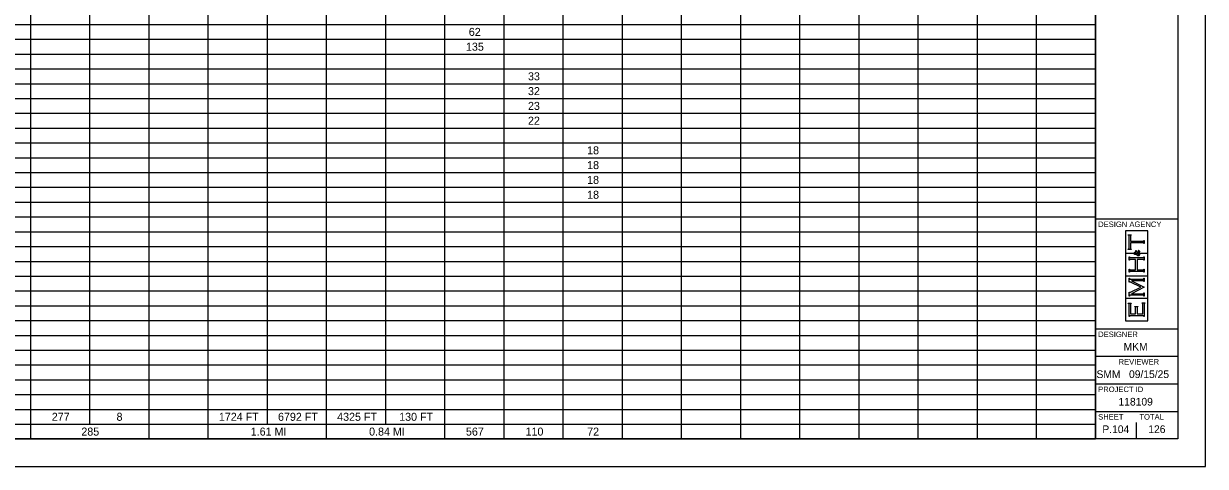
# Model space of a CAD drawing. Extents: x 0 to 34, y 0 to 22.
# Drawn here: x 12.5 to 34, y 0 to 8.05 of the extents above; entities that cross this region are included whole.
import ezdxf

# ---------------------------------------------------------------- set-up
doc = ezdxf.new("R2010")
doc.units = 0
for name, color, linetype in [('SH_Border', 7, 'Continuous'), ('SH_Cut_Line', 7, 'Continuous'), ('SH_Data', 7, 'Continuous'), ('SH_Text', 7, 'Continuous')]:
    doc.layers.add(name, color=color, linetype=linetype)

msp = doc.modelspace()

# ---------------------------------------------------------------- linework, layer by layer
at = {"layer": 'SH_Border'}
for p, q in [((32, 0.5), (32, 21.5)), ((32, 4.5), (33.5, 4.5)), ((32, 2.5), (33.5, 2.5)), ((32, 2), (33.5, 2)), ((32, 1.5), (33.5, 1.5)), ((32, 1), (33.5, 1))]:
    msp.add_line(p, q, dxfattribs=at)
msp.add_lwpolyline([(1.5, 21.5), (33.5, 21.5), (33.5, 0.5), (1.5, 0.5)], close=True, dxfattribs=at)
at = {"layer": 'SH_Cut_Line'}
msp.add_lwpolyline([(0, 0), (34, 0), (34, 22), (0, 22)], close=True, dxfattribs=at)
at = {"layer": 'SH_Data'}
for p, q in [((32.952, 4.279), (32.547, 4.279)), ((32.547, 4.279), (32.547, 3.875)), ((32.598, 4.204), (32.598, 4.211)), ((32.598, 4.211), (32.65, 4.211)), ((32.603, 4.203), (32.598, 4.204)), ((32.606, 4.201), (32.603, 4.203)), ((32.608, 4.199), (32.606, 4.201)), ((32.61, 4.196), (32.608, 4.199)), ((32.611, 4.192), (32.61, 4.196)), ((32.611, 4.187), (32.611, 4.192)), ((32.611, 3.968), (32.611, 4.187)), ((32.638, 4.196), (32.637, 4.192)), ((32.637, 4.192), (32.637, 4.187)), ((32.637, 4.187), (32.637, 4.093)), ((32.637, 4.093), (32.864, 4.093)), ((32.64, 4.199), (32.638, 4.196)), ((32.642, 4.201), (32.64, 4.199)), ((32.645, 4.203), (32.642, 4.201)), ((32.65, 4.204), (32.645, 4.203)), ((32.65, 4.211), (32.65, 4.204)), ((32.864, 4.093), (32.869, 4.093)), ((32.869, 4.093), (32.873, 4.094)), ((32.873, 4.094), (32.876, 4.096)), ((32.876, 4.096), (32.878, 4.097)), ((32.878, 4.097), (32.88, 4.101)), ((32.88, 4.101), (32.881, 4.106)), ((32.881, 4.106), (32.888, 4.106)), ((32.888, 4.106), (32.888, 4.048)), ((32.952, 3.875), (32.952, 4.279)), ((32.547, 3.875), (32.696, 3.875)), ((32.696, 3.869), (32.547, 3.869)), ((32.547, 3.869), (32.547, 3.465)), ((32.598, 3.95), (32.603, 3.951)), ((32.598, 3.944), (32.598, 3.95)), ((32.65, 3.944), (32.598, 3.944)), ((32.603, 3.951), (32.606, 3.953)), ((32.606, 3.953), (32.608, 3.955)), ((32.608, 3.955), (32.61, 3.958)), ((32.61, 3.958), (32.611, 3.962)), ((32.611, 3.962), (32.611, 3.968)), ((32.864, 4.061), (32.637, 4.061)), ((32.637, 4.061), (32.637, 3.968)), ((32.637, 3.968), (32.637, 3.962)), ((32.637, 3.962), (32.638, 3.958)), ((32.638, 3.958), (32.64, 3.955)), ((32.64, 3.955), (32.642, 3.953)), ((32.642, 3.953), (32.645, 3.951)), ((32.645, 3.951), (32.65, 3.95)), ((32.65, 3.95), (32.65, 3.944)), ((32.696, 3.875), (32.696, 3.869)), ((32.703, 3.879), (32.705, 3.883)), ((32.703, 3.873), (32.703, 3.879)), ((32.703, 3.868), (32.703, 3.873)), ((32.705, 3.883), (32.708, 3.887)), ((32.708, 3.887), (32.711, 3.89)), ((32.709, 3.879), (32.708, 3.876)), ((32.708, 3.876), (32.708, 3.873)), ((32.708, 3.873), (32.708, 3.869)), ((32.708, 3.869), (32.71, 3.866)), ((32.712, 3.881), (32.709, 3.879)), ((32.711, 3.89), (32.715, 3.892)), ((32.714, 3.883), (32.712, 3.881)), ((32.716, 3.884), (32.714, 3.883)), ((32.715, 3.892), (32.72, 3.892)), ((32.72, 3.884), (32.716, 3.884)), ((32.72, 3.892), (32.725, 3.892)), ((32.724, 3.884), (32.72, 3.884)), ((32.728, 3.882), (32.724, 3.884)), ((32.725, 3.892), (32.729, 3.89)), ((32.731, 3.88), (32.728, 3.882)), ((32.729, 3.89), (32.732, 3.887)), ((32.734, 3.877), (32.731, 3.88)), ((32.732, 3.887), (32.736, 3.883)), ((32.737, 3.872), (32.734, 3.877)), ((32.736, 3.883), (32.74, 3.878)), ((32.74, 3.867), (32.737, 3.872)), ((32.738, 3.893), (32.738, 3.922)), ((32.738, 3.922), (32.741, 3.922)), ((32.741, 3.893), (32.738, 3.893)), ((32.74, 3.878), (32.744, 3.869)), ((32.741, 3.922), (32.741, 3.918)), ((32.741, 3.918), (32.742, 3.915)), ((32.742, 3.896), (32.741, 3.895)), ((32.741, 3.895), (32.741, 3.893)), ((32.742, 3.915), (32.743, 3.913)), ((32.743, 3.897), (32.742, 3.896)), ((32.743, 3.913), (32.745, 3.911)), ((32.745, 3.899), (32.743, 3.897)), ((32.744, 3.869), (32.754, 3.875)), ((32.745, 3.911), (32.749, 3.908)), ((32.746, 3.899), (32.745, 3.899)), ((32.748, 3.899), (32.746, 3.899)), ((32.755, 3.899), (32.748, 3.899)), ((32.749, 3.908), (32.756, 3.904)), ((32.754, 3.875), (32.764, 3.881)), ((32.763, 3.895), (32.755, 3.899)), ((32.756, 3.904), (32.763, 3.9)), ((32.763, 3.9), (32.77, 3.896)), ((32.772, 3.887), (32.763, 3.895)), ((32.764, 3.881), (32.772, 3.887)), ((32.774, 3.872), (32.768, 3.867)), ((32.77, 3.896), (32.776, 3.891)), ((32.782, 3.878), (32.774, 3.872)), ((32.776, 3.891), (32.781, 3.895)), ((32.779, 3.923), (32.781, 3.926)), ((32.782, 3.922), (32.779, 3.923)), ((32.781, 3.926), (32.787, 3.924)), ((32.781, 3.895), (32.784, 3.898)), ((32.785, 3.921), (32.782, 3.922)), ((32.786, 3.873), (32.782, 3.878)), ((32.784, 3.898), (32.786, 3.901)), ((32.786, 3.919), (32.785, 3.921)), ((32.788, 3.917), (32.786, 3.919)), ((32.786, 3.901), (32.788, 3.904)), ((32.791, 3.886), (32.786, 3.881)), ((32.786, 3.881), (32.791, 3.876)), ((32.788, 3.869), (32.786, 3.873)), ((32.787, 3.924), (32.792, 3.921)), ((32.789, 3.914), (32.788, 3.917)), ((32.788, 3.904), (32.789, 3.908)), ((32.79, 3.867), (32.788, 3.869)), ((32.789, 3.911), (32.789, 3.914)), ((32.789, 3.908), (32.789, 3.911)), ((32.794, 3.89), (32.791, 3.886)), ((32.791, 3.876), (32.795, 3.87)), ((32.792, 3.921), (32.795, 3.918)), ((32.796, 3.894), (32.794, 3.89)), ((32.795, 3.918), (32.798, 3.914)), ((32.795, 3.87), (32.797, 3.866)), ((32.798, 3.897), (32.796, 3.894)), ((32.798, 3.914), (32.799, 3.91)), ((32.799, 3.901), (32.798, 3.897)), ((32.799, 3.91), (32.799, 3.905)), ((32.799, 3.905), (32.799, 3.901)), ((32.803, 3.869), (32.799, 3.875)), ((32.799, 3.875), (32.952, 3.875)), ((32.952, 3.869), (32.803, 3.869)), ((32.87, 4.061), (32.864, 4.061)), ((32.874, 4.06), (32.87, 4.061)), ((32.876, 4.059), (32.874, 4.06)), ((32.878, 4.057), (32.876, 4.059)), ((32.88, 4.053), (32.878, 4.057)), ((32.881, 4.048), (32.88, 4.053)), ((32.888, 4.048), (32.881, 4.048)), ((32.952, 3.465), (32.952, 3.869)), ((32.611, 3.749), (32.611, 3.807)), ((32.611, 3.807), (32.617, 3.807)), ((32.617, 3.749), (32.611, 3.749)), ((32.617, 3.807), (32.619, 3.802)), ((32.618, 3.754), (32.617, 3.749)), ((32.62, 3.758), (32.618, 3.754)), ((32.619, 3.802), (32.62, 3.798)), ((32.62, 3.798), (32.623, 3.797)), ((32.623, 3.76), (32.62, 3.758)), ((32.623, 3.797), (32.625, 3.795)), ((32.625, 3.761), (32.623, 3.76)), ((32.625, 3.795), (32.629, 3.794)), ((32.629, 3.762), (32.625, 3.761)), ((32.629, 3.794), (32.635, 3.794)), ((32.635, 3.762), (32.629, 3.762)), ((32.635, 3.794), (32.864, 3.794)), ((32.732, 3.762), (32.635, 3.762)), ((32.705, 3.863), (32.703, 3.868)), ((32.708, 3.858), (32.705, 3.863)), ((32.712, 3.853), (32.708, 3.858)), ((32.71, 3.866), (32.712, 3.864)), ((32.712, 3.864), (32.715, 3.862)), ((32.718, 3.85), (32.712, 3.853)), ((32.715, 3.862), (32.718, 3.861)), ((32.718, 3.861), (32.721, 3.861)), ((32.726, 3.85), (32.718, 3.85)), ((32.721, 3.861), (32.723, 3.861)), ((32.723, 3.861), (32.725, 3.862)), ((32.725, 3.862), (32.728, 3.862)), ((32.729, 3.85), (32.726, 3.85)), ((32.728, 3.862), (32.731, 3.863)), ((32.731, 3.85), (32.729, 3.85)), ((32.731, 3.863), (32.735, 3.865)), ((32.734, 3.851), (32.731, 3.85)), ((32.732, 3.572), (32.732, 3.762)), ((32.737, 3.852), (32.734, 3.851)), ((32.735, 3.865), (32.74, 3.867)), ((32.741, 3.853), (32.737, 3.852)), ((32.746, 3.855), (32.741, 3.853)), ((32.752, 3.844), (32.746, 3.855)), ((32.756, 3.86), (32.751, 3.857)), ((32.751, 3.857), (32.754, 3.852)), ((32.757, 3.837), (32.752, 3.844)), ((32.754, 3.852), (32.757, 3.848)), ((32.761, 3.863), (32.756, 3.86)), ((32.757, 3.848), (32.761, 3.845)), ((32.763, 3.833), (32.757, 3.837)), ((32.864, 3.762), (32.759, 3.762)), ((32.759, 3.762), (32.759, 3.572)), ((32.764, 3.865), (32.761, 3.863)), ((32.761, 3.845), (32.765, 3.843)), ((32.768, 3.829), (32.763, 3.833)), ((32.768, 3.867), (32.764, 3.865)), ((32.765, 3.843), (32.769, 3.841)), ((32.774, 3.827), (32.768, 3.829)), ((32.769, 3.841), (32.773, 3.841)), ((32.773, 3.841), (32.778, 3.841)), ((32.779, 3.827), (32.774, 3.827)), ((32.778, 3.841), (32.782, 3.843)), ((32.785, 3.827), (32.779, 3.827)), ((32.782, 3.843), (32.786, 3.846)), ((32.79, 3.829), (32.785, 3.827)), ((32.786, 3.846), (32.789, 3.849)), ((32.789, 3.849), (32.791, 3.853)), ((32.791, 3.864), (32.79, 3.867)), ((32.793, 3.834), (32.79, 3.829)), ((32.791, 3.861), (32.791, 3.864)), ((32.791, 3.859), (32.791, 3.861)), ((32.791, 3.853), (32.791, 3.859)), ((32.797, 3.838), (32.793, 3.834)), ((32.797, 3.866), (32.798, 3.861)), ((32.799, 3.844), (32.797, 3.838)), ((32.798, 3.861), (32.799, 3.857)), ((32.799, 3.857), (32.799, 3.852)), ((32.799, 3.852), (32.799, 3.844)), ((32.864, 3.794), (32.869, 3.794)), ((32.87, 3.762), (32.864, 3.762)), ((32.869, 3.794), (32.873, 3.795)), ((32.874, 3.761), (32.87, 3.762)), ((32.873, 3.795), (32.876, 3.797)), ((32.876, 3.76), (32.874, 3.761)), ((32.876, 3.797), (32.878, 3.798)), ((32.878, 3.758), (32.876, 3.76)), ((32.878, 3.798), (32.88, 3.802)), ((32.88, 3.754), (32.878, 3.758)), ((32.88, 3.802), (32.881, 3.807)), ((32.881, 3.749), (32.88, 3.754)), ((32.881, 3.807), (32.888, 3.807)), ((32.888, 3.749), (32.881, 3.749)), ((32.888, 3.807), (32.888, 3.749)), ((32.547, 3.465), (32.952, 3.465)), ((32.952, 3.459), (32.547, 3.459)), ((32.547, 3.459), (32.547, 3.055)), ((32.611, 3.527), (32.611, 3.585)), ((32.611, 3.585), (32.617, 3.585)), ((32.617, 3.527), (32.611, 3.527)), ((32.617, 3.585), (32.619, 3.58)), ((32.618, 3.532), (32.617, 3.527)), ((32.62, 3.536), (32.618, 3.532)), ((32.619, 3.58), (32.62, 3.576)), ((32.62, 3.576), (32.623, 3.574)), ((32.623, 3.537), (32.62, 3.536)), ((32.623, 3.574), (32.625, 3.573)), ((32.625, 3.539), (32.623, 3.537)), ((32.625, 3.573), (32.629, 3.572)), ((32.629, 3.54), (32.625, 3.539)), ((32.629, 3.572), (32.635, 3.572)), ((32.635, 3.54), (32.629, 3.54)), ((32.635, 3.572), (32.732, 3.572)), ((32.864, 3.54), (32.635, 3.54)), ((32.75, 3.5), (32.75, 3.5)), ((32.759, 3.572), (32.864, 3.572)), ((32.864, 3.572), (32.87, 3.572)), ((32.87, 3.54), (32.864, 3.54)), ((32.87, 3.572), (32.874, 3.573)), ((32.874, 3.539), (32.87, 3.54)), ((32.874, 3.573), (32.876, 3.574)), ((32.876, 3.538), (32.874, 3.539)), ((32.876, 3.574), (32.878, 3.576)), ((32.878, 3.536), (32.876, 3.538)), ((32.878, 3.576), (32.88, 3.58)), ((32.88, 3.532), (32.878, 3.536)), ((32.88, 3.58), (32.881, 3.585)), ((32.881, 3.527), (32.88, 3.532)), ((32.881, 3.585), (32.888, 3.585)), ((32.888, 3.527), (32.881, 3.527)), ((32.888, 3.585), (32.888, 3.527)), ((32.952, 3.055), (32.952, 3.459)), ((32.611, 3.345), (32.611, 3.418)), ((32.611, 3.418), (32.617, 3.418)), ((32.617, 3.345), (32.611, 3.345)), ((32.617, 3.418), (32.619, 3.412)), ((32.62, 3.352), (32.617, 3.345)), ((32.619, 3.412), (32.62, 3.409)), ((32.62, 3.409), (32.623, 3.407)), ((32.622, 3.355), (32.62, 3.352)), ((32.626, 3.355), (32.622, 3.355)), ((32.623, 3.407), (32.625, 3.405)), ((32.625, 3.405), (32.629, 3.405)), ((32.629, 3.355), (32.626, 3.355)), ((32.629, 3.405), (32.635, 3.405)), ((32.633, 3.353), (32.629, 3.355)), ((32.64, 3.35), (32.633, 3.353)), ((32.635, 3.405), (32.864, 3.405)), ((32.825, 3.257), (32.64, 3.35)), ((32.641, 3.165), (32.825, 3.257)), ((32.864, 3.373), (32.654, 3.373)), ((32.654, 3.373), (32.888, 3.255)), ((32.888, 3.255), (32.654, 3.138)), ((32.864, 3.405), (32.869, 3.405)), ((32.87, 3.373), (32.864, 3.373)), ((32.869, 3.405), (32.873, 3.405)), ((32.874, 3.372), (32.87, 3.373)), ((32.873, 3.405), (32.876, 3.407)), ((32.876, 3.37), (32.874, 3.372)), ((32.876, 3.407), (32.878, 3.409)), ((32.878, 3.369), (32.876, 3.37)), ((32.878, 3.409), (32.88, 3.412)), ((32.88, 3.365), (32.878, 3.369)), ((32.88, 3.412), (32.881, 3.418)), ((32.881, 3.36), (32.88, 3.365)), ((32.881, 3.418), (32.888, 3.418)), ((32.888, 3.36), (32.881, 3.36)), ((32.888, 3.418), (32.888, 3.36)), ((32.547, 3.055), (32.952, 3.055)), ((32.952, 3.049), (32.547, 3.049)), ((32.547, 3.049), (32.547, 2.645)), ((32.611, 3.096), (32.611, 3.168)), ((32.611, 3.168), (32.617, 3.168)), ((32.617, 3.096), (32.611, 3.096)), ((32.617, 3.168), (32.62, 3.162)), ((32.618, 3.102), (32.617, 3.096)), ((32.62, 3.105), (32.618, 3.102)), ((32.62, 3.162), (32.622, 3.158)), ((32.623, 3.107), (32.62, 3.105)), ((32.622, 3.158), (32.626, 3.158)), ((32.625, 3.109), (32.623, 3.107)), ((32.629, 3.109), (32.625, 3.109)), ((32.626, 3.158), (32.627, 3.158)), ((32.627, 3.158), (32.633, 3.161)), ((32.635, 3.109), (32.629, 3.109)), ((32.633, 3.161), (32.641, 3.165)), ((32.864, 3.109), (32.635, 3.109)), ((32.654, 3.138), (32.864, 3.138)), ((32.864, 3.138), (32.869, 3.138)), ((32.87, 3.109), (32.864, 3.109)), ((32.869, 3.138), (32.873, 3.139)), ((32.874, 3.109), (32.87, 3.109)), ((32.873, 3.139), (32.876, 3.141)), ((32.876, 3.107), (32.874, 3.109)), ((32.876, 3.141), (32.878, 3.143)), ((32.878, 3.105), (32.876, 3.107)), ((32.878, 3.143), (32.88, 3.146)), ((32.88, 3.102), (32.878, 3.105)), ((32.88, 3.146), (32.881, 3.151)), ((32.881, 3.096), (32.88, 3.102)), ((32.881, 3.151), (32.888, 3.151)), ((32.888, 3.096), (32.881, 3.096)), ((32.888, 3.151), (32.888, 3.096)), ((32.952, 2.645), (32.952, 3.049)), ((32.598, 2.962), (32.598, 2.969)), ((32.598, 2.969), (32.65, 2.969)), ((32.603, 2.961), (32.598, 2.962)), ((32.606, 2.959), (32.603, 2.961)), ((32.608, 2.957), (32.606, 2.959)), ((32.61, 2.955), (32.608, 2.957)), ((32.611, 2.951), (32.61, 2.955)), ((32.611, 2.945), (32.611, 2.951)), ((32.611, 2.725), (32.611, 2.945)), ((32.64, 2.957), (32.638, 2.955)), ((32.638, 2.955), (32.638, 2.951)), ((32.638, 2.951), (32.638, 2.945)), ((32.638, 2.945), (32.638, 2.77)), ((32.642, 2.959), (32.64, 2.957)), ((32.645, 2.961), (32.642, 2.959)), ((32.65, 2.962), (32.645, 2.961)), ((32.65, 2.969), (32.65, 2.962)), ((32.719, 2.902), (32.719, 2.908)), ((32.719, 2.908), (32.772, 2.908)), ((32.724, 2.901), (32.719, 2.902)), ((32.728, 2.899), (32.724, 2.901)), ((32.729, 2.896), (32.728, 2.899)), ((32.731, 2.894), (32.729, 2.896)), ((32.732, 2.89), (32.731, 2.894)), ((32.732, 2.884), (32.732, 2.89)), ((32.732, 2.77), (32.732, 2.884)), ((32.76, 2.894), (32.759, 2.89)), ((32.759, 2.89), (32.759, 2.884)), ((32.759, 2.884), (32.759, 2.77)), ((32.761, 2.896), (32.76, 2.894)), ((32.763, 2.899), (32.761, 2.896)), ((32.767, 2.901), (32.763, 2.899)), ((32.772, 2.902), (32.767, 2.901)), ((32.772, 2.908), (32.772, 2.902)), ((32.848, 2.965), (32.848, 2.972)), ((32.848, 2.972), (32.901, 2.972)), ((32.853, 2.964), (32.848, 2.965)), ((32.857, 2.962), (32.853, 2.964)), ((32.859, 2.96), (32.857, 2.962)), ((32.86, 2.958), (32.859, 2.96)), ((32.861, 2.953), (32.86, 2.958)), ((32.861, 2.948), (32.861, 2.953)), ((32.861, 2.77), (32.861, 2.948)), ((32.889, 2.957), (32.888, 2.953)), ((32.888, 2.953), (32.888, 2.948)), ((32.888, 2.948), (32.888, 2.725)), ((32.891, 2.96), (32.889, 2.957)), ((32.892, 2.962), (32.891, 2.96)), ((32.896, 2.964), (32.892, 2.962)), ((32.901, 2.965), (32.896, 2.964)), ((32.901, 2.972), (32.901, 2.965)), ((32.547, 2.645), (32.952, 2.645)), ((32.617, 2.725), (32.611, 2.725)), ((32.619, 2.73), (32.617, 2.725)), ((32.62, 2.734), (32.619, 2.73)), ((32.623, 2.735), (32.62, 2.734)), ((32.625, 2.737), (32.623, 2.735)), ((32.629, 2.738), (32.625, 2.737)), ((32.635, 2.738), (32.629, 2.738)), ((32.864, 2.738), (32.635, 2.738)), ((32.638, 2.77), (32.732, 2.77)), ((32.759, 2.77), (32.861, 2.77)), ((32.87, 2.738), (32.864, 2.738)), ((32.874, 2.737), (32.87, 2.738)), ((32.876, 2.735), (32.874, 2.737)), ((32.878, 2.734), (32.876, 2.735)), ((32.88, 2.73), (32.878, 2.734)), ((32.881, 2.725), (32.88, 2.73)), ((32.888, 2.725), (32.881, 2.725)), ((32.375, 0.675), (32.375, 0.675)), ((32.75, 0.5), (32.75, 0.8))]:
    msp.add_line(p, q, dxfattribs=at)
at = {"layer": 'SH_Text'}
for p, q in [((12.627, 21.501), (12.627, 0.498)), ((13.703, 21.501), (13.703, 0.767)), ((14.779, 21.501), (14.779, 0.498)), ((15.856, 21.501), (15.856, 0.498)), ((16.932, 21.501), (16.932, 0.767)), ((18.008, 21.501), (18.008, 0.498)), ((19.085, 21.501), (19.085, 0.767)), ((20.161, 21.501), (20.161, 0.498)), ((21.237, 21.501), (21.237, 0.498)), ((22.313, 21.501), (22.313, 0.498)), ((23.39, 21.501), (23.39, 0.498)), ((24.466, 21.501), (24.466, 0.498)), ((25.542, 21.501), (25.542, 0.498)), ((26.619, 21.501), (26.619, 0.498)), ((27.695, 21.501), (27.695, 0.498)), ((28.771, 21.501), (28.771, 0.498)), ((29.847, 21.501), (29.847, 0.498)), ((30.924, 21.501), (30.924, 0.498)), ((32, 21.501), (32, 0.498)), ((1.5, 8.032), (32, 8.032)), ((1.5, 7.763), (32, 7.763)), ((1.5, 7.493), (32, 7.493)), ((1.5, 7.224), (32, 7.224)), ((1.5, 6.955), (32, 6.955)), ((1.5, 6.686), (32, 6.686)), ((1.5, 6.417), (32, 6.417)), ((1.5, 6.148), (32, 6.148)), ((1.5, 5.879), (32, 5.879)), ((1.5, 5.61), (32, 5.61)), ((1.5, 5.341), (32, 5.341)), ((1.5, 5.072), (32, 5.072)), ((1.5, 4.803), (32, 4.803)), ((1.5, 4.534), (32, 4.534)), ((1.5, 4.265), (32, 4.265)), ((1.5, 3.996), (32, 3.996)), ((1.5, 3.726), (32, 3.726)), ((1.5, 3.457), (32, 3.457)), ((1.5, 3.188), (32, 3.188)), ((1.5, 2.919), (32, 2.919)), ((1.5, 2.65), (32, 2.65)), ((1.5, 2.381), (32, 2.381)), ((1.5, 2.112), (32, 2.112)), ((1.5, 1.843), (32, 1.843)), ((1.5, 1.574), (32, 1.574)), ((1.5, 1.305), (32, 1.305)), ((8.923, 1.036), (12.627, 1.036)), ((12.627, 1.036), (32, 1.036)), ((1.5, 0.767), (32, 0.767)), ((1.5, 0.498), (32, 0.498))]:
    msp.add_line(p, q, dxfattribs=at)

# ---------------------------------------------------------------- texts
at = {"layer": 'SH_Data'}
for s, height, p in [('DESIGN AGENCY', 0.1, (32.05, 4.35)), ('DESIGNER', 0.1, (32.05, 2.35)), ('MKM', 0.14, (32.513, 2.105)), ('REVIEWER', 0.1, (32.422, 1.85)), ('SMM', 0.14, (32.02, 1.605)), ('09/15/25', 0.14, (32.611, 1.605)), ('PROJECT ID', 0.1, (32.05, 1.35)), ('118109', 0.14, (32.42, 1.105)), ('SHEET', 0.1, (32.05, 0.85)), ('TOTAL', 0.1, (32.8, 0.85)), ('P.104', 0.14, (32.126, 0.605)), ('126', 0.14, (32.962, 0.605))]:
    msp.add_text(s, height=height, dxfattribs=at).set_placement(p)
at = {"layer": 'SH_Text'}
for s, height, p in [('62', 0.1456, (20.602, 7.824)), ('135', 0.1456, (20.55, 7.555)), ('33', 0.1456, (21.678, 7.017)), ('32', 0.1456, (21.678, 6.748)), ('23', 0.1456, (21.678, 6.479)), ('22', 0.1456, (21.678, 6.21)), ('18', 0.1456, (22.754, 5.672)), ('18', 0.1456, (22.754, 5.403)), ('18', 0.1456, (22.754, 5.134)), ('18', 0.1456, (22.754, 4.864)), ('277', 0.1456, (13.016, 0.828)), ('8', 0.146, (14.194, 0.828)), ('1724 FT', 0.1456, (16.055, 0.828)), ('6792 FT', 0.1456, (17.131, 0.828)), ('4325 FT', 0.1456, (18.207, 0.828)), ('130 FT', 0.1456, (19.335, 0.828)), ('285', 0.1456, (13.554, 0.559)), ('1.61 MI', 0.1456, (16.635, 0.559)), ('0.84 MI', 0.1456, (18.788, 0.559)), ('567', 0.1456, (20.55, 0.559)), ('110', 0.1456, (21.634, 0.559)), ('72', 0.1456, (22.755, 0.559))]:
    msp.add_text(s, height=height, dxfattribs=at).set_placement(p)

doc.saveas('drawing.dxf')
